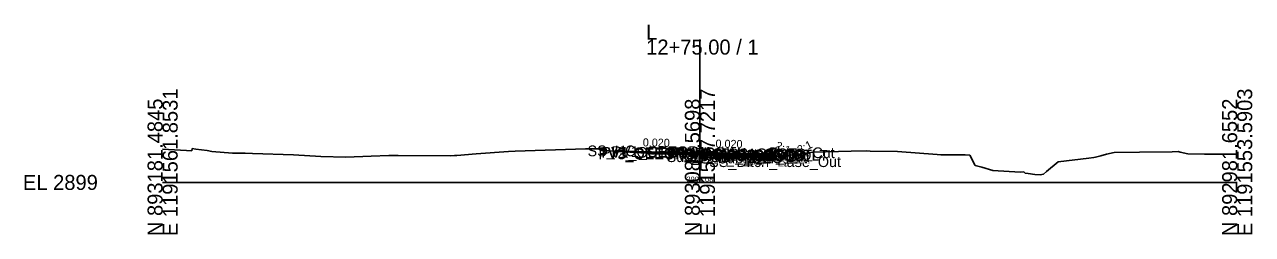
# Model space of a CAD drawing. Extents: x -26 to 203, y -10 to 7027.
# Drawn here: x -25.7 to 202.8, y 5490.3 to 5529.4 of the extents above; entities that cross this region are included whole.
import ezdxf

# ---------------------------------------------------------------- set-up
doc = ezdxf.new("R2010")
doc.units = 0
for name, color, linetype in [('Default', 7, 'Continuous'), ('Exist CMT Pavement', 7, 'Continuous'), ('Exist Cross Section Cell', 7, 'Continuous'), ('Exist XS Center Line Elevation Label', 7, 'Continuous'), ('Exist XS Ground Line', 7, 'Continuous'), ('Prop CMT Concrete Structures', 7, 'Continuous'), ('Prop CMT Pvmt Course 1', 7, 'Continuous'), ('Prop CMT Pvmt Course 2', 7, 'Continuous'), ('Prop CMT Pvmt Course 2 Wedge', 7, 'Continuous'), ('Prop CMT Pvmt Course 3', 7, 'Continuous'), ('Prop CMT Pvmt Course 3 Wedge', 7, 'Continuous'), ('Prop CMT Pvmt Surface', 7, 'Continuous'), ('Prop CMT Pvmt Surface Shoulder', 7, 'Continuous'), ('Prop CMT Pvmt Wedge Surface 3', 7, 'Continuous'), ('Prop CMT Shld Paved Course 1', 7, 'Continuous'), ('Prop CMT Shld Paved Course 2', 7, 'Continuous'), ('Prop CMT Shld Paved Course 3', 7, 'Continuous'), ('Prop CMT Slope Grass', 7, 'Continuous'), ('Prop CMT Subgrade Earthwork', 7, 'Continuous'), ('Scratch_Level_6', 7, 'Continuous')]:
    doc.layers.add(name, color=color, linetype=linetype)

msp = doc.modelspace()

# ---------------------------------------------------------------- linework, layer by layer
at = {"layer": 'Exist CMT Pavement'}
for points in [[(110.51, 5505.12), (112.13, 5505.08), (112.34, 5504.87)], [(110.51, 5504.91), (110.51, 5505.12)], [(112.34, 5504.87), (110.51, 5504.91)]]:
    msp.add_lwpolyline(points, dxfattribs=at)
at = {"layer": 'Exist Cross Section Cell'}
for p, q in [((100, 5500), (100, 5526.6)), ((0, 5500), (100, 5500)), ((100, 5500), (200, 5500))]:
    msp.add_line(p, q, dxfattribs=at)
at = {"layer": 'Exist XS Center Line Elevation Label'}
msp.add_lwpolyline([(100, 5505.33), (91, 5505.51)], dxfattribs=at)
at = {"layer": 'Exist XS Ground Line'}
msp.add_lwpolyline([(100, 5505.41), (91, 5505.59)], dxfattribs=at)
at = {"layer": 'Prop CMT Concrete Structures'}
for points in [[(91, 5505.72), (83.31, 5505.87)], [(100, 5505.53), (91, 5505.72)], [(100, 5505.53), (110.51, 5505.32)]]:
    msp.add_lwpolyline(points, dxfattribs=at)
at = {"layer": 'Prop CMT Pvmt Course 1'}
for points in [[(100, 5505.53), (91, 5505.72)], [(91, 5505.72), (91, 5505.59)], [(91, 5505.59), (100, 5505.41)], [(100, 5505.41), (100, 5505.53)], [(100, 5505.53), (110.51, 5505.32)], [(100, 5505.33), (100, 5505.53)], [(110.51, 5505.12), (100, 5505.33)], [(100, 5505.12), (100, 5505.33)], [(100, 5505.33), (110.51, 5505.12)], [(110.51, 5504.91), (100, 5505.12)], [(110.51, 5505.32), (110.51, 5505.12)], [(110.51, 5505.12), (110.51, 5504.91)]]:
    msp.add_lwpolyline(points, dxfattribs=at)
at = {"layer": 'Prop CMT Pvmt Course 2'}
msp.add_lwpolyline([(100, 5505.12), (91, 5505.3)], dxfattribs=at)
at = {"layer": 'Prop CMT Pvmt Course 3'}
for points in [[(100, 5505.12), (110.51, 5504.91)], [(100, 5504.79), (100, 5505.12)], [(110.51, 5504.57), (100, 5504.79)], [(110.51, 5504.91), (110.51, 5504.57)]]:
    msp.add_lwpolyline(points, dxfattribs=at)
at = {"layer": 'Prop CMT Pvmt Course 3 Wedge'}
for p, q in [((0, 5506.2), (4.47, 5505.93)), ((4.47, 5505.93), (5.45, 5505.88)), ((5.45, 5505.88), (5.52, 5506.3)), ((5.52, 5506.3), (6.18, 5506.17)), ((6.18, 5506.17), (8.32, 5505.91)), ((8.32, 5505.91), (9.15, 5505.73)), ((9.15, 5505.73), (13.04, 5505.44)), ((13.04, 5505.44), (15.35, 5505.43)), ((15.35, 5505.43), (16.71, 5505.38)), ((16.71, 5505.38), (24.39, 5505.15)), ((58.35, 5505.3), (64.37, 5505.74)), ((64.37, 5505.74), (65.61, 5505.81)), ((65.61, 5505.81), (78.72, 5506.22)), ((78.72, 5506.22), (81.3, 5506.25)), ((81.3, 5506.25), (81.64, 5506.26)), ((81.64, 5506.26), (82.11, 5505.96)), ((82.11, 5505.96), (84.94, 5505.75)), ((84.94, 5505.75), (92.05, 5505.31)), ((116.81, 5505.1), (120.67, 5505.57)), ((120.67, 5505.57), (121.02, 5505.6)), ((121.02, 5505.6), (128.17, 5505.84)), ((128.17, 5505.84), (130.99, 5505.85)), ((130.99, 5505.85), (131.72, 5505.83)), ((131.72, 5505.83), (136.78, 5505.74)), ((136.78, 5505.74), (144.16, 5505.21)), ((175.65, 5505.27), (177.09, 5505.57)), ((177.09, 5505.57), (181.79, 5505.65)), ((181.79, 5505.65), (187.91, 5505.72)), ((187.91, 5505.72), (189.02, 5505.73)), ((189.02, 5505.73), (189.41, 5505.64)), ((189.41, 5505.64), (190.84, 5505.3)), ((24.39, 5505.15), (29.44, 5504.83)), ((29.44, 5504.83), (34.1, 5504.69)), ((34.1, 5504.69), (38.8, 5504.87)), ((38.8, 5504.87), (42.11, 5505)), ((42.11, 5505), (43.87, 5504.99)), ((43.87, 5504.99), (53.51, 5504.92)), ((53.51, 5504.92), (54.32, 5505.02)), ((54.32, 5505.02), (54.75, 5505.03)), ((54.75, 5505.03), (58.35, 5505.3)), ((92.05, 5505.31), (96.32, 5505.18)), ((96.32, 5505.18), (100, 5505.08)), ((100, 5505.08), (100.92, 5505.06)), ((100.92, 5505.06), (106.43, 5504.88)), ((106.43, 5504.88), (110.05, 5504.74)), ((110.05, 5504.74), (111.64, 5504.59)), ((111.64, 5504.59), (112.38, 5504.51)), ((112.38, 5504.51), (113.61, 5504.68)), ((113.61, 5504.68), (116.81, 5505.1)), ((144.16, 5505.21), (144.87, 5505.15)), ((144.87, 5505.15), (147.28, 5505.13)), ((147.28, 5505.13), (149.4, 5505.11)), ((149.4, 5505.11), (150.24, 5505.09)), ((150.24, 5505.09), (151.25, 5503.17)), ((151.25, 5503.17), (152.47, 5502.81)), ((164.52, 5502.05), (166.66, 5503.82)), ((166.66, 5503.82), (172.42, 5504.51)), ((172.42, 5504.51), (173.32, 5504.65)), ((173.32, 5504.65), (173.63, 5504.7)), ((173.63, 5504.7), (174.63, 5504.93)), ((174.63, 5504.93), (175.65, 5505.27)), ((190.84, 5505.3), (193.91, 5505.27)), ((193.91, 5505.27), (200, 5505.27)), ((152.47, 5502.81), (154.53, 5502.21)), ((154.53, 5502.21), (159.6, 5501.9)), ((159.6, 5501.9), (160.3, 5501.99)), ((160.3, 5501.99), (160.54, 5501.75)), ((160.54, 5501.75), (161.1, 5501.68)), ((161.1, 5501.68), (162.32, 5501.45)), ((162.32, 5501.45), (163.34, 5501.42)), ((163.34, 5501.42), (163.95, 5501.53)), ((163.95, 5501.53), (164.52, 5502.05))]:
    msp.add_line(p, q, dxfattribs=at)
at = {"layer": 'Prop CMT Pvmt Surface'}
msp.add_lwpolyline([(111.92, 5505.3), (114.51, 5505.09), (116.96, 5503.86), (120.26, 5505.52)], dxfattribs=at)
at = {"layer": 'Prop CMT Pvmt Surface Shoulder'}
msp.add_lwpolyline([(110.51, 5505.32), (111.92, 5505.3)], dxfattribs=at)
at = {"layer": 'Prop CMT Shld Paved Course 1'}
for points in [[(91, 5505.59), (91, 5505.72)], [(100, 5505.41), (91, 5505.59)], [(100, 5505.41), (100, 5505.53)], [(110.51, 5505.32), (111.92, 5505.3), (112.13, 5505.08)], [(110.51, 5505.12), (110.51, 5505.32)], [(112.13, 5505.08), (110.51, 5505.12)]]:
    msp.add_lwpolyline(points, dxfattribs=at)
at = {"layer": 'Prop CMT Shld Paved Course 2'}
for points in [[(91, 5505.51), (91, 5505.72)], [(100, 5505.33), (91, 5505.51)], [(100, 5505.33), (100, 5505.53)]]:
    msp.add_lwpolyline(points, dxfattribs=at)
at = {"layer": 'Prop CMT Shld Paved Course 3'}
for points in [[(91, 5505.3), (91, 5505.72)], [(100, 5505.12), (100, 5505.53)], [(100, 5505.12), (91, 5505.3)]]:
    msp.add_lwpolyline(points, dxfattribs=at)
at = {"layer": 'Prop CMT Slope Grass'}
for points in [[(110.51, 5504.91), (112.34, 5504.87), (112.84, 5504.86), (113.18, 5504.52)], [(110.51, 5504.57), (110.51, 5504.91)], [(113.18, 5504.52), (110.51, 5504.57)]]:
    msp.add_lwpolyline(points, dxfattribs=at)
at = {"layer": 'Prop CMT Subgrade Earthwork'}
for points in [[(100, 5504.79), (110.51, 5504.57)], [(110.51, 5504.57), (113.18, 5504.52)], [(113.18, 5504.52), (113.81, 5505.15)]]:
    msp.add_lwpolyline(points, dxfattribs=at)

# ---------------------------------------------------------------- texts
at = {"layer": 'Default'}
msp.add_text('-', height=0.0001, dxfattribs=at).set_placement((0, 5500))
at = {"layer": 'Exist Cross Section Cell'}
for s, p in [('L', (90, 5526.6)), ('12+75.00 / 1', (90, 5523.8)), ('EL 2899', (-26, 5498.6))]:
    msp.add_text(s, height=2.8, dxfattribs=at).set_placement(p)
for s, p in [('E 1191561.8531', (2.8, 5490)), ('E 1191557.7217', (102.8, 5490)), ('E 1191553.5903', (202.8, 5490)), ('N 893181.4845', (0, 5490)), ('N 893081.5698', (100, 5490)), ('N 892981.6552', (200, 5490))]:
    msp.add_text(s, height=2.8, rotation=90, dxfattribs=at).set_placement(p)
at = {"layer": 'Prop CMT Pvmt Course 2 Wedge'}
for s, p in [('SS_HC', (79.09, 5504.87)), ('PV2_OEEOP_W', (81.11, 5504.51)), ('PV3_OEEOP_W', (81.11, 5504.3)), ('PV1_OEEOP_W', (81.68, 5504.59)), ('PV1_OEEOP', (83.57, 5504.72)), ('PV1_PGL_W', (92.58, 5504.41)), ('Sub_PGL', (93.81, 5503.79)), ('PV2_PGL', (93.91, 5504.33)), ('PV3_PGL', (93.91, 5504.12)), ('PV1_PGL', (94.47, 5504.53)), ('Sub_Trench_Out_DLT', (96.96, 5504.04)), ('Sub_Trench_Out', (100.08, 5503.52)), ('PS3_Shelf_Out', (101.52, 5503.86)), ('Sub_OEOT', (103.29, 5503.57)), ('PV2_OEOT', (103.38, 5504.12)), ('PV3_OEOT', (103.38, 5503.91)), ('PV1_OEOT', (103.95, 5504.32)), ('PS2_OEOP', (105.06, 5504.08)), ('PS3_OEOP', (105.27, 5503.87)), ('PS1_OEOP', (105.41, 5504.3)), ('GS_OS_CTL', (106.58, 5504.09)), ('Slope_Cut', (112.6, 5504.52)), ('SS_Ditch_Base_Out', (101.73, 5502.86))]:
    msp.add_text(s, height=2, dxfattribs=at).set_placement(p)
at = {"layer": 'Prop CMT Pvmt Surface Shoulder'}
for p in [(89.36, 5506.71), (102.9, 5506.48)]:
    msp.add_text('0.020', height=1.5, rotation=358.8542, dxfattribs=at).set_placement(p)
at = {"layer": 'Prop CMT Pvmt Wedge Surface 3'}
for rotation, p in [(26.5651, (118.59, 5505.29)), (333.4349, (113.86, 5506.39))]:
    msp.add_text('2:1', height=1.5, rotation=rotation, dxfattribs=at).set_placement(p)
at = {"layer": 'Scratch_Level_6'}
msp.add_text('2904.08', height=1, dxfattribs=at).set_placement((97.5, 5500.08))

doc.saveas('drawing.dxf')
